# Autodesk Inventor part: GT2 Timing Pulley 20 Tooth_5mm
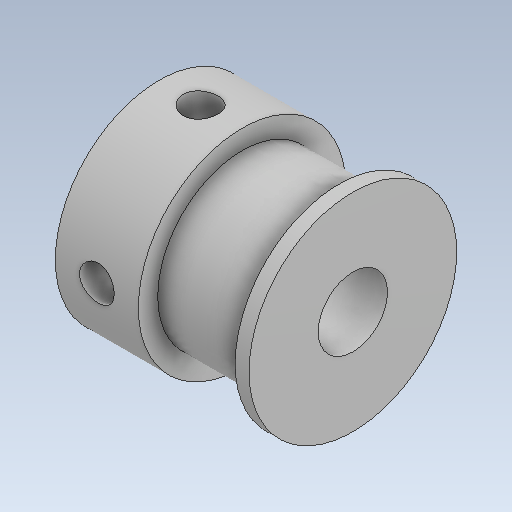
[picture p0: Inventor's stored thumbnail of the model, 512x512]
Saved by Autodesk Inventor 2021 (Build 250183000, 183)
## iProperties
Created: 2026-10
Part Number: GT2 Timing Pulley 20 Tooth_5mm
Material: Steel
Document SubType Name: Modeling
Designer: hp
Density: 7.85 g/cm^3
Appearance: Default
Author: hp
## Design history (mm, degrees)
feature "Body1"
body "Solid1"
